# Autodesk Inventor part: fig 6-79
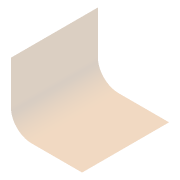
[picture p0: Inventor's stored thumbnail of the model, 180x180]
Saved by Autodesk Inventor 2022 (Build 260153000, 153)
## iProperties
Part Number: fig 6-79
Document SubType Name: Modeling
Created: 2003-10
Designer: Owner
Manufacturer: Standard
Standards Organization: Custom
Density: 1 g/cm^3
Material: Generic
Appearance: Default
Control State: 0
Master: False
Checked Out: False
Shininess: 64.0
Length Units: 11269
Angle Units: 11279
Time Units: 11290
Mass Units: 11283
Length Display Precision: 3
Angle Display Precision: 2
Compacted: True
Density: 0.0
Volumn: 0.0
Area: 0.0
PropertySet Name: Model Information
Author: Owner
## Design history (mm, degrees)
node "Sketch1"
sketch "Sketch2"
  geometry: L1 (22.777, 31.862)-(22.777, 0.2); L2 (7.777, -14.8)-(-29.161, -14.8); A1 r 15 centre (7.777, 0.2) between (7.777, -14.8) and (22.777, 0.2)
  constraints: 4 end point, 2 point on circle, 2 tangent, 1 centre point, 1 perpendicular, 1 vertical
  dimensions: "d23" = 15 radius of A1
extrude_surface "ExtrusionSrf1" sketch "Sketch2" dims "d24" = 63.5, "d25" = 0
body "Srf1"
